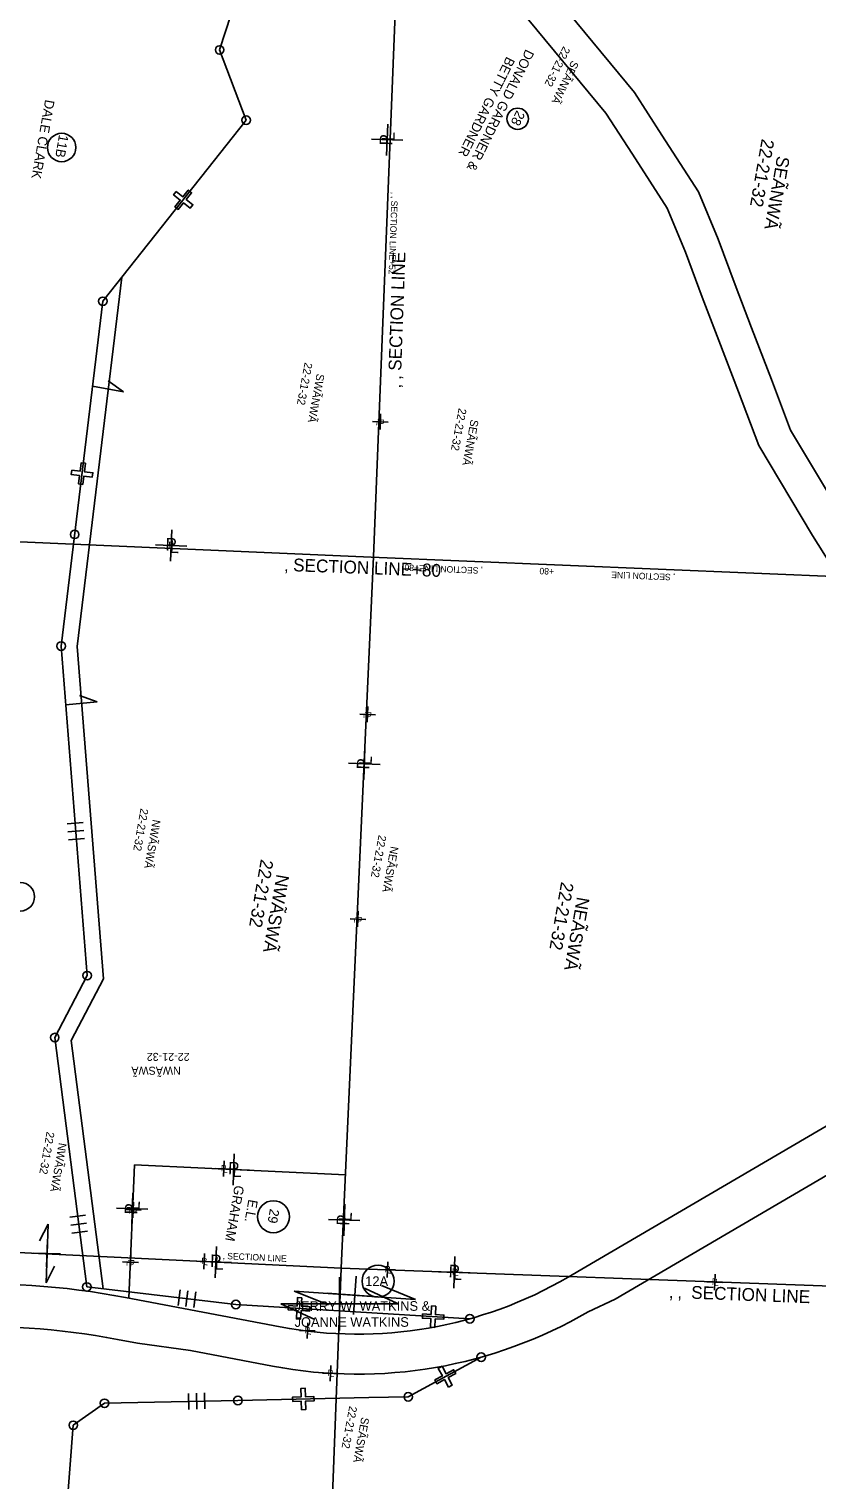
# Model space of a CAD drawing. Extents: x 2814293 to 2835768, y 121185 to 156337.
# Drawn here: x 2821428 to 2822904, y 131914 to 134634 of the extents above; entities that cross this region are included whole.
import ezdxf

# ---------------------------------------------------------------- set-up
doc = ezdxf.new("R2010")
doc.units = 0
for name, color, linetype in [('Photo-Retaining wall', 7, 'Continuous'), ('Roadway-Alignment notes', 7, 'Continuous'), ('Roadway-Ditches', 7, 'Continuous'), ('Roadway-Edge of pavement', 7, 'Continuous'), ('Roadway-Edge of shoulder', 7, 'Continuous'), ('Roadway-Entrances', 7, 'Continuous'), ('Roadway-Existing Easement', 7, 'Continuous'), ('Roadway-New rw', 7, 'Continuous'), ('Roadway-Permanent easement', 7, 'Continuous'), ('Roadway-Safety', 7, 'Continuous'), ('Roadway-Walls', 7, 'Continuous'), ('Scratch-2', 7, 'Continuous'), ('Scratch-5', 7, 'Continuous'), ('Text-New rw label', 7, 'Continuous'), ('Traffic_Control-Traffic barriers', 7, 'Continuous')]:
    doc.layers.add(name, color=color, linetype=linetype)

msp = doc.modelspace()

# ---------------------------------------------------------------- linework, layer by layer
at = {"layer": 'Roadway-Ditches'}
for centre, radius in [((2822343.1, 134465.8), 20), ((2821488.8, 134412), 26.7), ((2821411.3, 133007.6), 26.7), ((2821885.5, 132407.9), 30), ((2822081.5, 132287), 30)]:
    msp.add_circle(centre, radius, dxfattribs=at)
at = {"layer": 'Roadway-Edge of pavement'}
for p, q in [((2821447.4, 132362.7), (2821463.3, 132393.9)), ((2821463.3, 132393.9), (2821459.4, 132283.9)), ((2821460.5, 132313.9), (2821462.2, 132363.9)), ((2821436.4, 132339.8), (2821486.4, 132338)), ((2821475.3, 132315.1), (2821459.4, 132283.9)), ((2821461.4, 132338.9), (2821461.4, 132338.9)), ((2822035.7, 132224.8), (2822040.6, 132296.7)), ((2821924.4, 132268.6), (2822151.9, 132252.9)), ((2821988.5, 132242.8), (2821924.4, 132268.6)), ((2822089.9, 132257.2), (2821986.4, 132264.3)), ((2822038.1, 132260.8), (2822038.1, 132260.8)), ((2822087.8, 132278.7), (2822151.9, 132252.9))]:
    msp.add_line(p, q, dxfattribs=at)
at = {"layer": 'Roadway-Edge of shoulder'}
for p, q in [((2822097.6, 134397.1), (2822099.6, 134456)), ((2822069.2, 134427.6), (2822128.1, 134425.5)), ((2821695, 133695.4), (2821692.7, 133636.6)), ((2821664.4, 133667.1), (2821723.3, 133664.9)), ((2822054.8, 133227.3), (2822056.9, 133286.2)), ((2822026.4, 133257.8), (2822085.3, 133255.7)), ((2821812.2, 132525.9), (2821810.1, 132467)), ((2821781.7, 132497.5), (2821840.6, 132495.4)), ((2821620, 132393.3), (2821622, 132452.2)), ((2821591.6, 132423.8), (2821650.5, 132421.7)), ((2822017.1, 132372.3), (2822019.2, 132431.2)), ((2821988.7, 132402.8), (2822047.6, 132400.7)), ((2821778.7, 132352.3), (2821776.6, 132293.4)), ((2821748.2, 132323.9), (2821807.1, 132321.8)), ((2822225.5, 132333), (2822223.2, 132274.2)), ((2822194.9, 132304.8), (2822253.8, 132302.5))]:
    msp.add_line(p, q, dxfattribs=at)
at = {"layer": 'Roadway-Entrances'}
for p, q in [((2822231.2, 137625.3), (2822073.3, 133645.3)), ((2821575.9, 133974.4), (2821604.6, 133954.3)), ((2821604.6, 133954.3), (2821546.6, 133964.5)), ((2822068.5, 133644.1), (2820747.1, 133702.4)), ((2822073.3, 133645.3), (2822012.3, 132311.3)), ((2823399.5, 133588.1), (2822068.5, 133644.1)), ((2821522.3, 133384.7), (2821555.2, 133372.8)), ((2821555.2, 133372.8), (2821496.6, 133367.6)), ((2822012.3, 132311.3), (2820692.1, 132375.8)), ((2822012.3, 132311.3), (2821962.5, 130985.5)), ((2822012.3, 132311.3), (2823345.6, 132262.5))]:
    msp.add_line(p, q, dxfattribs=at)
at = {"layer": 'Roadway-Existing Easement'}
for points in [[(2822160.1, 135001.6), (2822561.8, 134515.3), (2822613.4, 134435.4), (2822681.9, 134329.2), (2822719, 134240.3), (2822750.8, 134154.7), (2822781.5, 134073.7), (2822818.7, 133977.3), (2822854.4, 133882.2), (2822951.6, 133719.6), (2823021.3, 133609.2), (2823072.9, 133528.1), (2823120.1, 133454), (2823221.9, 133292.4), (2823310.9, 133147.7), (2823353.3, 133015.4), (2823369.6, 132922.1), (2823386.3, 132818.9), (2823397.7, 132751.1)], [(2822105.7, 134963.9), (2822508.4, 134476.2), (2822558, 134399.6), (2822623.3, 134298.3), (2822657.6, 134216.1), (2822689, 134131.5), (2822719.9, 134050.1), (2822757, 133953.8), (2822794.7, 133853.4), (2822895.4, 133685), (2822965.6, 133573.8), (2823017.2, 133492.6), (2823064.4, 133418.6), (2823165.9, 133257.5), (2823250.4, 133119.9), (2823289.1, 132999.5), (2823304.5, 132911.2), (2823321.2, 132808.1), (2823332.7, 132740.1)]]:
    msp.add_lwpolyline(points, dxfattribs=at)
at = {"layer": 'Roadway-New rw'}
for p, q in [((2821784.7, 134594.9), (2821870.7, 134861.8)), ((2821834.4, 134463.2), (2821784.7, 134594.9)), ((2821565.8, 134123.8), (2821834.4, 134463.2)), ((2821487.9, 133477.6), (2821565.8, 134123.8)), ((2821536.7, 132859.8), (2821487.9, 133477.6)), ((2821498.9, 133144.3), (2821528.8, 133146.8)), ((2821500.2, 133129.4), (2821530.1, 133131.9)), ((2821501.4, 133114.4), (2821531.3, 133116.9)), ((2821475.7, 132743.6), (2821536.7, 132859.8)), ((2821475.7, 132743.6), (2821535.8, 132276.2)), ((2821503.8, 132406.8), (2821533.6, 132410.7)), ((2821505.8, 132392), (2821535.5, 132395.8)), ((2821507.7, 132377.1), (2821537.4, 132380.9)), ((2821815.2, 132243.4), (2821535.8, 132276.2)), ((2821710.6, 132271.1), (2821706.8, 132241.3)), ((2821725.4, 132269.2), (2821721.6, 132239.4)), ((2821740.3, 132267.3), (2821736.5, 132237.5)), ((2822253.4, 132216.5), (2821815.2, 132243.4)), ((2822274.8, 132144.6), (2822138.2, 132070.3)), ((2821726.1, 132076.6), (2821727, 132046.6)), ((2821741.1, 132077), (2821742, 132047)), ((2821756.1, 132077.5), (2821757, 132047.5)), ((2822064, 132069), (2822138.2, 132070.3)), ((2821510.5, 132016.9), (2821569.1, 132058.1)), ((2821569.1, 132058.1), (2821819, 132063.5)), ((2821819, 132063.5), (2822064, 132069)), ((2821510.5, 132016.9), (2821456.6, 131319.7))]:
    msp.add_line(p, q, dxfattribs=at)
for points in [[(2821703.5, 134329.7), (2821698.5, 134323.4), (2821711, 134313.4), (2821701, 134301), (2821707.2, 134295.9), (2821717.2, 134308.4), (2821729.7, 134298.4), (2821734.7, 134304.6), (2821722.2, 134314.7), (2821732.2, 134327.1), (2821726, 134332.1), (2821716, 134319.7), (2821703.5, 134329.7)], [(2821507.5, 133807.1), (2821506.5, 133799.1), (2821522.4, 133797.2), (2821520.5, 133781.3), (2821528.4, 133780.4), (2821530.3, 133796.2), (2821546.2, 133794.3), (2821547.2, 133802.3), (2821531.3, 133804.2), (2821533.2, 133820.1), (2821525.3, 133821), (2821523.4, 133805.1), (2821507.5, 133807.1)], [(2821938.6, 132255.9), (2821930.6, 132256.3), (2821929.7, 132240.3), (2821913.8, 132241.2), (2821913.3, 132233.2), (2821929.3, 132232.4), (2821928.5, 132216.4), (2821936.5, 132216), (2821937.3, 132231.9), (2821953.3, 132231.1), (2821953.7, 132239.1), (2821937.7, 132239.9), (2821938.6, 132255.9)], [(2822189.9, 132240.4), (2822181.9, 132240.8), (2822181, 132224.8), (2822165.1, 132225.6), (2822164.6, 132217.6), (2822180.6, 132216.8), (2822179.8, 132200.8), (2822187.8, 132200.4), (2822188.6, 132216.4), (2822204.6, 132215.6), (2822205, 132223.5), (2822189, 132224.4), (2822189.9, 132240.4)], [(2822213.5, 132088.5), (2822220.6, 132092.3), (2822212.9, 132106.4), (2822227, 132114), (2822223.1, 132121.1), (2822209.1, 132113.4), (2822201.4, 132127.5), (2822194.4, 132123.6), (2822202.1, 132109.6), (2822188, 132101.9), (2822191.8, 132094.9), (2822205.9, 132102.6), (2822213.5, 132088.5)], [(2821938, 132046.1), (2821946, 132046.3), (2821945.6, 132062.3), (2821961.6, 132062.7), (2821961.4, 132070.7), (2821945.4, 132070.3), (2821945, 132086.3), (2821937, 132086.1), (2821937.4, 132070.1), (2821921.4, 132069.8), (2821921.6, 132061.8), (2821937.6, 132062.1), (2821938, 132046.1)]]:
    msp.add_lwpolyline(points, close=True, dxfattribs=at)
for centre in [(2821487.9, 133477.6), (2821815.2, 132243.4), (2822253.4, 132216.5), (2822274.8, 132144.6), (2821819, 132063.5)]:
    msp.add_circle(centre, 8.13, dxfattribs=at)
at = {"layer": 'Roadway-Permanent easement'}
for p, q in [((2821518, 133476.9), (2821601.5, 134168.9)), ((2821567.3, 132853.5), (2821518, 133476.9)), ((2821506.7, 132738), (2821567.3, 132853.5)), ((2821506.7, 132738), (2821566.5, 132272.6))]:
    msp.add_line(p, q, dxfattribs=at)
at = {"layer": 'Roadway-Walls'}
for p, q in [((2822100.4, 133897.4), (2822071, 133898.5)), ((2822086.2, 133912.7), (2822085.2, 133883.2)), ((2821694.4, 133680.7), (2821693.3, 133651.3)), ((2821679.1, 133666.5), (2821708.6, 133665.5)), ((2822076.5, 133348.8), (2822047.1, 133349.8)), ((2822062.3, 133364), (2822061.3, 133334.6)), ((2822044.3, 132980.4), (2822043.3, 132951)), ((2822058.5, 132965.2), (2822029.1, 132966.2)), ((2821793, 132512.4), (2821792, 132483)), ((2821777.8, 132498.2), (2821807.2, 132497.2)), ((2821623.2, 132435.3), (2821622.1, 132405.8)), ((2821637.4, 132420), (2821607.9, 132421.1)), ((2821632.4, 132322.1), (2821603, 132323.1)), ((2821618.2, 132337.3), (2821617.2, 132307.9)), ((2821741.1, 132324.6), (2821770.5, 132323.5)), ((2821756.3, 132338.8), (2821755.3, 132309.3)), ((2822100, 132323.2), (2822098.9, 132293.8)), ((2822225.8, 132318.4), (2822224.6, 132289)), ((2822084.7, 132309), (2822114.2, 132308)), ((2822210.5, 132304.2), (2822239.9, 132303.1)), ((2822712.9, 132299.9), (2822711.8, 132270.4)), ((2822697.6, 132285.7), (2822727, 132284.6)), ((2821949.7, 132209), (2821948.7, 132179.5)), ((2821934.5, 132194.8), (2821963.9, 132193.7)), ((2821992.8, 132129), (2821991.7, 132099.6)), ((2821977.5, 132114.8), (2822007, 132113.8))]:
    msp.add_line(p, q, dxfattribs=at)
at = {"layer": 'Scratch-2'}
for p, q in [((2822009.5, 132194.5), (2822009.5, 132294.5)), ((2822056.1, 132274), (2822119.5, 132244.5)), ((2821899.5, 132244.5), (2822119.5, 132244.5)), ((2821962.9, 132214.9), (2821899.5, 132244.5)), ((2822059.5, 132244.5), (2821959.5, 132244.5)), ((2822009.5, 132244.5), (2822009.5, 132244.5))]:
    msp.add_line(p, q, dxfattribs=at)
at = {"layer": 'Text-New rw label'}
for centre in [(2821784.7, 134594.9), (2821834.4, 134463.2), (2821565.8, 134123.8), (2821513.1, 133686.9), (2821536.7, 132859.8), (2821475.7, 132743.6), (2821535.8, 132276.2), (2822138.2, 132070.3), (2821569.1, 132058.1), (2821510.5, 132016.9)]:
    msp.add_circle(centre, 8, dxfattribs=at)
at = {"layer": 'Traffic_Control-Traffic barriers'}
for p, q in [((2822437.5, 132294.6), (2823054.8, 132655.8)), ((2821614.6, 132255.2), (2821625.1, 132505.4)), ((2821625.1, 132505.4), (2822020.3, 132486.1)), ((2821608.4, 132256.4), (2821898, 132201.4))]:
    msp.add_line(p, q, dxfattribs=at)
for points in [[(2822475.3, 132229.8), (2822525.9, 132253.6), (2823095.2, 132586.8)], [(2821593.5, 132177.8), (2821631.1, 132170.7), (2821730.2, 132156.9), (2821884, 132127.7)]]:
    msp.add_lwpolyline(points, dxfattribs=at)
for centre, radius, start, end in [((2822043.4, 132967.8), 780.1, 259.2528, 300.3374), ((2821332.7, 130802.8), 1479.6, 79.2581, 92.9636), ((2822043.4, 132967.8), 855.1, 259.2529, 300.3373), ((2821332.7, 130802.8), 1399.5, 79.2583, 92.9634)]:
    msp.add_arc(centre, radius, start, end, dxfattribs=at)
for points in [[(2820745, 134137.3), (2820759.2, 134187.4), (2820796.5, 134319.8), (2820866, 134561), (2820882.3, 134622.2), (2820890.5, 134685.3), (2820890.5, 134756.7), (2820883.9, 134860.9), (2820877.2, 134984), (2820874.1, 135053.3), (2820875.7, 135099.8), (2820890.4, 135198), (2820908.8, 135318.4), (2820918.2, 135358.7), (2820947.2, 135415), (2820971.2, 135442.6), (2820998.7, 135473.5), (2821025.3, 135502.5), (2821045.1, 135531.8), (2821070.8, 135598.4), (2821079.3, 135649.1), (2821097, 135745.4), (2821119.8, 135882.3), (2821158.7, 136055), (2821178.4, 136223.5), (2821188.3, 136310.9), (2821206, 136399.5), (2821239.2, 136501.5), (2821280.2, 136573.3), (2821318.6, 136629.4), (2821360.8, 136683.1), (2821415, 136745), (2821441.8, 136778.8), (2821466.2, 136818.9), (2821496.5, 136874.2), (2821527.4, 136933.2), (2821577.1, 137015.9), (2821617.9, 137081.8), (2821646.4, 137114.1), (2821689.7, 137146.1), (2821742.9, 137169.7), (2821819.5, 137196), (2821916.7, 137230), (2821964, 137251.9), (2821999.5, 137272.8), (2822036.2, 137299.3), (2822066.7, 137332.1), (2822140.5, 137422.7), (2822185.2, 137482.3), (2822198.9, 137509), (2822215.2, 137563.4), (2822229.1, 137614.9), (2822248, 137660.6), (2822266.7, 137699.3), (2822292.7, 137735.3), (2822310.6, 137759.8), (2822332.2, 137793.7), (2822385.8, 137897), (2822427.2, 137981.4), (2822444, 138030.2), (2822454.4, 138055.9), (2822465.5, 138103.9), (2822468, 138144.1), (2822470.8, 138205.9), (2822474.8, 138257), (2822483.6, 138296.3), (2822497, 138347.3), (2822557.6, 138490), (2822586.2, 138571.2), (2822602.9, 138636.9), (2822615, 138753.6), (2822619.1, 138791.9)], [(2820421.9, 132323.7), (2820430.3, 132339.5), (2820446.6, 132365.4), (2820477.5, 132409.8), (2820521.7, 132462.2), (2820581.9, 132544.8), (2820633.7, 132622.6), (2820678.7, 132698.5), (2820711.5, 132765.4), (2820823.8, 132974.3), (2820869.5, 133062.1), (2820906.1, 133146.6), (2820945.5, 133258.7), (2820956.4, 133356.9), (2820952.7, 133425), (2820927.9, 133503.2), (2820893.9, 133557.3), (2820809, 133702.5), (2820771.2, 133774.3), (2820745.5, 133846.6), (2820736.3, 133904.7), (2820741, 133953.4), (2820747.2, 134000.7), (2820776.6, 134101.6), (2820833.7, 134304.6), (2820904.5, 134550.3), (2820921.6, 134614.4), (2820930.5, 134682.7), (2820930.5, 134758), (2820923.8, 134863.3), (2820917.2, 134986), (2820914.2, 135053.6), (2820915.6, 135096.1), (2820930, 135192), (2820948.1, 135310.8), (2820956, 135344.7), (2820980.6, 135392.4), (2821001.2, 135416.1), (2821028.4, 135446.7), (2821056.8, 135477.7), (2821080.7, 135513.2), (2821109.6, 135587.8), (2821118.7, 135642.2), (2821136.4, 135738.5), (2821159.1, 135874.6), (2821198.2, 136048.3), (2821218.1, 136218.9), (2821227.9, 136304.7), (2821244.8, 136389.4), (2821276, 136485.3), (2821314.1, 136552.1), (2821350.9, 136605.8), (2821391.6, 136657.6), (2821445.7, 136719.4), (2821474.7, 136755.9), (2821500.8, 136798.9), (2821531.8, 136855.4), (2821562.3, 136913.6), (2821611.3, 136995.1), (2821650.2, 137057.9), (2821673.5, 137084.5), (2821709.9, 137111.3), (2821757.5, 137132.5), (2821832.5, 137158.2), (2821931.7, 137192.9), (2821982.6, 137216.4), (2822021.4, 137239.3), (2822062.8, 137269.2), (2822096.8, 137305.8), (2822172, 137398.1), (2822219.2, 137461.1), (2822236.1, 137494), (2822253.7, 137552.5), (2822267, 137602), (2822284.6, 137644.3), (2822301.1, 137678.7), (2822325.1, 137711.8), (2822343.7, 137737.3), (2822366.9, 137773.8), (2822421.5, 137879), (2822464.2, 137966.1), (2822481.4, 138016.2), (2822492.6, 138043.8), (2822505.3, 138098.1), (2822507.9, 138141.9), (2822510.7, 138203.4), (2822514.5, 138251), (2822522.5, 138286.8), (2822534.9, 138334.4), (2822594.9, 138475.5), (2822624.6, 138559.6), (2822642.4, 138629.9), (2822654.8, 138749.4), (2822658.9, 138787.6)]]:
    msp.add_open_spline(points, degree=3, dxfattribs=at)

# ---------------------------------------------------------------- texts
at = {"layer": 'Photo-Retaining wall'}
for s, rotation, p in [('22-21-32', 243.5041, (2822428.9, 134602.7)), ('SEÃNWÃ', 243.5041, (2822444.8, 134576.2)), ('22-21-32', 259.5041, (2821944.1, 134009.8)), ('SWÃNWÃ', 259.5041, (2821966.6, 133988.8)), ('22-21-32', 259.5041, (2822232.7, 133924.1)), ('SEÃNWÃ', 259.5041, (2822255.3, 133903)), ('22-21-32', 260.038, (2821636.7, 133173.9)), ('NWÃSWÃ', 260.038, (2821659.4, 133153.1)), ('22-21-32', 259.5041, (2822082.7, 133124.1)), ('NEÃSWÃ', 259.5041, (2822105.3, 133103)), ('22-21-32', 180.038, (2821728.5, 132715)), ('NWÃSWÃ', 180.038, (2821711.9, 132689)), ('22-21-32', 260.038, (2821460.7, 132568)), ('NWÃSWÃ', 260.038, (2821483.4, 132547.2)), ('22-21-32', 259.5041, (2822027.8, 132053.8)), ('SEÃSWÃ', 259.5041, (2822050.4, 132032.8))]:
    msp.add_text(s, height=15, rotation=rotation, dxfattribs=at).set_placement(p)
at = {"layer": 'Roadway-Alignment notes'}
for s, p in [('22-21-32', (2822800.5, 134429.3)), ('SEÃNWÃ', (2822829.4, 134397.3)), ('22-21-32', (2821862, 133078.8)), ('NWÃSWÃ', (2821891.6, 133050.8)), ('22-21-32', (2822424.7, 133036.4)), ('NEÃSWÃ', (2822454.3, 133008.4))]:
    msp.add_text(s, height=24, rotation=260.038, dxfattribs=at).set_placement(p)
at = {"layer": 'Roadway-Ditches'}
for s, rotation, p in [('BETTY GARDNER', 243.5041, (2822322.6, 134583.6)), ('DONALD GARDNER &', 243.5041, (2822358.6, 134597.4)), ('DALE CLARK', 260.038, (2821457.9, 134502.6)), ('28', 243.5041, (2822341.5, 134482.7)), ('11B', 260.038, (2821484, 134436.9)), ('GRAHAM', 260.038, (2821813, 132467.6)), ('E.L.', 260.038, (2821838.8, 132441.2)), ('29', 260.038, (2821879.1, 132423.5)), ('12A', 0.038, (2822057.5, 132278)), ('JERRY W. WATKINS &', 0.038, (2821925.2, 132231.4)), ('JOANNE WATKINS', 0.038, (2821925.2, 132201.4))]:
    msp.add_text(s, height=18, rotation=rotation, dxfattribs=at).set_placement(p)
at = {"layer": 'Roadway-Edge of shoulder'}
for s, rotation, p in [('L', 87.9775, (2822112.4, 134423.4)), ('P', 87.9775, (2822107.9, 134415.5)), ('P', 357.7804, (2821682.8, 133656.8)), ('L', 357.7804, (2821690.7, 133652.2)), ('L', 87.9775, (2822069.6, 133253.6)), ('P', 87.9775, (2822065.1, 133245.7)), ('P', 357.9775, (2821800.1, 132487.2)), ('L', 357.9775, (2821808, 132482.6)), ('P', 87.9775, (2821630.3, 132411.7)), ('L', 87.9775, (2821634.8, 132419.6)), ('P', 87.9775, (2822027.4, 132390.7)), ('L', 87.9775, (2822032, 132398.6)), ('P', 357.9775, (2821766.6, 132313.6)), ('L', 357.9775, (2821774.5, 132309)), ('P', 357.7804, (2822213.3, 132294.4)), ('L', 357.7804, (2822221.1, 132289.8))]:
    msp.add_text(s, height=23.6, rotation=rotation, dxfattribs=at).set_placement(p)
at = {"layer": 'Roadway-Safety'}
for s, rotation, p in [('‚ ‚ SECTION LINE+52', 267.9775, (2822106.8, 134328.7)), ('‚ SECTION LINE+80', 177.7804, (2822277.9, 133624.9)), ('+80', 177.5329, (2822411.4, 133623.1)), ('‚ SECTION LINE', 177.7804, (2822638.1, 133612.4)), ('‚ ‚ SECTION LINE', 357.3804, (2821782.7, 132329))]:
    msp.add_text(s, height=12, rotation=rotation, dxfattribs=at).set_placement(p)
at = {"layer": 'Roadway-Walls'}
for s, rotation, p in [('L', 267.9775, (2822078.8, 133899.5)), ('P', 267.9775, (2822081.1, 133903.5)), ('P', 357.9775, (2821688.4, 133661.4)), ('L', 357.9775, (2821692.3, 133659.1)), ('L', 267.9775, (2822054.9, 133350.9)), ('P', 267.9775, (2822057.2, 133354.8)), ('P', 267.9775, (2822039.2, 132971.2)), ('L', 267.9775, (2822036.9, 132967.3)), ('P', 357.9775, (2821787, 132493.1)), ('L', 357.9775, (2821790.9, 132490.8)), ('P', 267.9775, (2821618, 132426.1)), ('L', 267.9775, (2821615.7, 132422.1)), ('L', 267.9775, (2821610.8, 132324.2)), ('P', 267.9775, (2821613.1, 132328.1)), ('P', 357.9775, (2821750.3, 132319.4)), ('L', 357.9775, (2821754.2, 132317.2)), ('P', 357.9775, (2822093.9, 132303.9)), ('L', 357.9775, (2822097.8, 132301.6)), ('P', 357.7804, (2822219.7, 132299.1)), ('L', 357.7804, (2822223.6, 132296.8)), ('P', 357.7804, (2822706.8, 132280.5)), ('L', 357.7804, (2822710.7, 132278.2)), ('P', 357.9775, (2821943.7, 132189.6)), ('L', 357.9775, (2821947.6, 132187.3)), ('P', 357.9775, (2821986.7, 132109.7)), ('L', 357.9775, (2821990.7, 132107.4))]:
    msp.add_text(s, height=11.8, rotation=rotation, dxfattribs=at).set_placement(p)
at = {"layer": 'Scratch-5'}
for s, rotation, p in [('‚ ‚ SECTION LINE', 87.9775, (2822123.9, 133961.1)), ('‚ SECTION LINE+80', 357.7804, (2821906, 133618.4)), ('‚ ‚  SECTION LINE', 357.7804, (2822626.9, 132255.9))]:
    msp.add_text(s, height=24, rotation=rotation, dxfattribs=at).set_placement(p)

doc.saveas('drawing.dxf')
